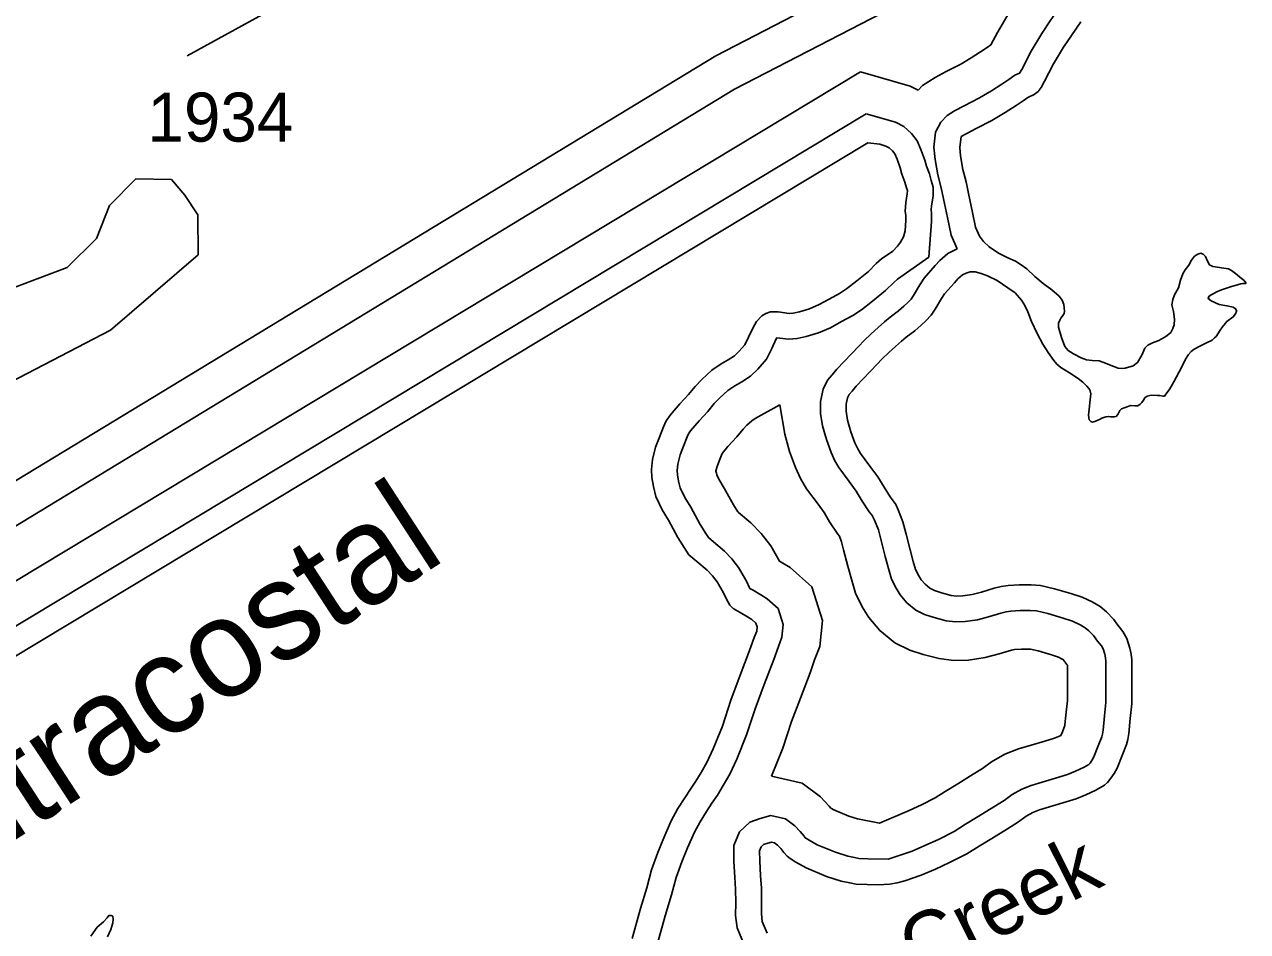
# Model space of a CAD drawing. Extents: x 2104537 to 2336408, y 34176 to 229611.
# Drawn here: x 2136862 to 2139980, y 43568 to 45881 of the extents above; entities that cross this region are included whole.
import ezdxf

# ---------------------------------------------------------------- set-up
doc = ezdxf.new("R2010")
doc.units = 0
for name, color, linetype in [('Exist Hydrographic Buffer Line', 7, 'Continuous'), ('Exist Hydrographic Creek Single Shore', 7, 'Continuous'), ('Exist Hydrographic Intracoastal Waterway Label', 7, 'Continuous'), ('Exist Hydrographic Misc Water Feature', 7, 'Continuous'), ('Exist Hydrographic River Shore', 7, 'Continuous'), ('Exist Road Secondary Type 51 Attributed', 7, 'Continuous'), ('Exist Road Secondary Type 51 Number Label', 7, 'Continuous'), ('Old_Level_32', 7, 'Continuous')]:
    doc.layers.add(name, color=color, linetype=linetype)

msp = doc.modelspace()

# ---------------------------------------------------------------- linework, layer by layer
at = {"layer": 'Exist Hydrographic Buffer Line'}
for p, q in [((2136210.3, 44335.1), (2138624.3, 45801.3)), ((2136263.7, 44252.4), (2138672.5, 45715.5))]:
    msp.add_line(p, q, dxfattribs=at)
for points in [[(2138624.3, 45801.3), (2139896.7, 46459.7), (2140167.9, 46542.5)], [(2139433.5, 45999.8), (2139396.3, 45945.9), (2139372.5, 45911.1), (2139342.3, 45860.3), (2139325.9, 45828.6), (2139316.7, 45822.6), (2139299.5, 45810.9), (2139275.7, 45795.4), (2139249.2, 45779.7), (2139212.1, 45760.8), (2139183.4, 45745.4), (2139151.6, 45725), (2139140.1, 45713.1)], [(2139506.6, 45932.4), (2139477.4, 45890.1), (2139455.5, 45858.1), (2139428.3, 45812.5), (2139404.4, 45766.1), (2139399.1, 45757.1), (2139387.2, 45751.2), (2139371.6, 45740.8), (2139353.9, 45728.9), (2139327.6, 45711.8), (2139296.7, 45693.5), (2139257.8, 45673.6), (2139233.2, 45660.4), (2139214.5, 45648.4), (2139198.6, 45631.9), (2139185, 45605.9), (2139180.3, 45567.7), (2139183.5, 45536.8), (2139190.3, 45497.2), (2139198.8, 45464.7), (2139204.8, 45435.9), (2139215, 45388.2), (2139224.2, 45343.6), (2139239.7, 45309)], [(2135551.7, 43635), (2135826.5, 43851.3), (2138993.8, 45759.8)], [(2138993.8, 45759.8), (2139119.7, 45723.8), (2139140.1, 45713.1)], [(2135662.8, 43597.1), (2135882.5, 43770.1), (2139007.9, 45653.4)], [(2139007.9, 45653.4), (2139082.9, 45631.9), (2139104.3, 45620.7), (2139123.8, 45602.8), (2139137.6, 45583.8), (2139147.4, 45562.1), (2139157.5, 45534.5), (2139161.3, 45519.5), (2139169.1, 45499.9), (2139173.8, 45482.9), (2139178.8, 45466.3), (2139178.3, 45443.1), (2139174.2, 45418.5), (2139173.2, 45407.8), (2139174.7, 45399.6), (2139174.8, 45378.6), (2139167.3, 45287.1)], [(2139167.3, 45287.1), (2139088.1, 45231.6), (2139078.6, 45223.1), (2139057.4, 45202.1), (2139024.4, 45175.4), (2138995.8, 45153.4), (2138973.9, 45138.8), (2138945.2, 45123.2), (2138916.7, 45107.4), (2138886.1, 45094.3), (2138854.6, 45084.9), (2138831.7, 45079.7), (2138810.1, 45078), (2138780.4, 45082), (2138778.8, 45078.8), (2138767, 45054.7), (2138753.4, 45027.1), (2138731.6, 45001.6), (2138712.7, 44984.3), (2138691, 44969.7), (2138672.9, 44959.5), (2138655.3, 44947.7), (2138634.7, 44928.7), (2138620.7, 44913.9), (2138604, 44894), (2138581.7, 44869.7), (2138560.4, 44844.6), (2138555.2, 44837.3), (2138551.5, 44829.3), (2138542.3, 44805.2), (2138533.7, 44783), (2138527.9, 44759.6), (2138526.1, 44743.4), (2138526.6, 44732.6), (2138529.7, 44716.4), (2138533.8, 44699.2), (2138545.4, 44674.4), (2138560.7, 44649.5), (2138584.3, 44606), (2138599, 44582.6), (2138605.7, 44572.4), (2138618.5, 44561.2), (2138646.9, 44537.5), (2138665.6, 44518.1), (2138682.7, 44496.1), (2138702.6, 44461.5), (2138710.8, 44443.8), (2138711.5, 44442.5), (2138719.8, 44438), (2138739.6, 44426), (2138755.6, 44416.2), (2138783.9, 44391.3), (2138796.6, 44350.7), (2138793, 44317.9), (2138784.1, 44294.5), (2138772.3, 44261.3), (2138748.2, 44197.9), (2138724.9, 44135.7), (2138703, 44069.1), (2138677.8, 44007), (2138660.2, 43968.7), (2138643.5, 43939.7), (2138628.9, 43915.4), (2138614.6, 43894.7), (2138601.2, 43873.4), (2138584.5, 43847.7), (2138570, 43821), (2138552.5, 43780.8), (2138537.7, 43745.1), (2138523.1, 43705.5), (2138511.9, 43661.1), (2138495.8, 43608), (2138475.5, 43536.7)], [(2139239.7, 45309), (2139216.4, 45296.6), (2139195.6, 45278.9), (2139183.9, 45265.9)], [(2139183.9, 45265.9), (2139155.9, 45233.9), (2139144.4, 45216.9)], [(2139144.4, 45216.9), (2139128.3, 45189.7), (2139122.3, 45180.6), (2139113.8, 45171.7), (2139103.6, 45162.2), (2139090.6, 45150.4), (2139068.9, 45134.7), (2139054.9, 45122.3), (2139038.7, 45108.3), (2139020.6, 45091.6), (2139002.1, 45073.8), (2138989.1, 45060.6), (2138932.9, 45001.9), (2138921.3, 44987.4), (2138909.4, 44973.4), (2138898, 44951), (2138891.2, 44919.6), (2138891.1, 44888.9), (2138896.5, 44857.6), (2138906.4, 44822.2), (2138918.5, 44789.1), (2138928.1, 44768.4), (2138938.1, 44751), (2138964.5, 44715.6), (2138982.5, 44690.7), (2138998, 44665.5), (2139015.8, 44638.3), (2139024.1, 44627.5), (2139024.4, 44627), (2139029.2, 44616.8), (2139039.1, 44592.3), (2139045.9, 44565.2), (2139056.4, 44524.2), (2139064.7, 44493.2), (2139072.8, 44466.4), (2139084.4, 44443.1), (2139094.6, 44426.3), (2139111.7, 44406.1), (2139134.6, 44387.4), (2139157, 44376.5), (2139181.3, 44368.1), (2139212.1, 44360.3), (2139236, 44357.3), (2139260.1, 44357.9), (2139291.4, 44362.8), (2139320.1, 44370.1), (2139351.6, 44379.9), (2139364.5, 44383.1), (2139376.4, 44384.7), (2139400.6, 44386.2), (2139425.8, 44386.5), (2139441.9, 44385.1), (2139471.4, 44378.3), (2139510, 44366.9), (2139534.2, 44359), (2139553.8, 44349.9), (2139566.5, 44342.5), (2139575.7, 44334.7), (2139587.7, 44322.3), (2139597.6, 44308.5), (2139608, 44295.8), (2139612.2, 44288.3), (2139616.5, 44274.8), (2139618.1, 44265.5), (2139619.2, 44256.8), (2139619.3, 44219.1), (2139619.2, 44178.8), (2139619.3, 44151.7), (2139615.9, 44117.6), (2139612.2, 44081.4), (2139610.4, 44071.1), (2139608.7, 44064.3), (2139599.7, 44040.9), (2139588.4, 44013), (2139583.9, 44005.1), (2139578.7, 43997.2), (2139575.4, 43993.2), (2139563.7, 43986.4), (2139541.7, 43976.5), (2139521.1, 43967.8), (2139491, 43959), (2139456.9, 43948.8), (2139428.3, 43940.2), (2139404.4, 43930.6), (2139380.5, 43917.2), (2139359.3, 43901.9), (2139333.2, 43885.5), (2139293.5, 43860.8), (2139261.5, 43841), (2139232.1, 43822.5), (2139191.9, 43802.3), (2139157.8, 43786.7), (2139125, 43772.4), (2139063.9, 43752.1)], [(2139063.9, 43752.1), (2139012.3, 43753.1), (2138989.6, 43754.1), (2138978.3, 43756.1), (2138961.1, 43759.6), (2138929.3, 43769.8), (2138883, 43789.1), (2138862.6, 43800.4), (2138851.6, 43807.6), (2138849.4, 43810.4), (2138839.5, 43822.7), (2138825.8, 43837), (2138802.3, 43854.6), (2138765.1, 43863.2), (2138737.6, 43855.9), (2138711.2, 43846.5), (2138685.2, 43821.6), (2138670.6, 43787), (2138670.8, 43745.8), (2138672.8, 43705.8), (2138675.1, 43675.3), (2138675.3, 43641.9), (2138675, 43608.7), (2138678.9, 43576.6), (2138696.6, 43533.5)]]:
    msp.add_lwpolyline(points, dxfattribs=at)
at = {"layer": 'Exist Hydrographic Creek Single Shore'}
for points in [[(2138672.5, 45715.5), (2139934, 46368.1), (2140187.4, 46445.5)], [(2139555.4, 45887.6), (2139531.4, 45852.9), (2139510.8, 45822.8), (2139485.7, 45780.6), (2139461.9, 45734.5), (2139453.7, 45720.5), (2139446, 45710.2), (2139436, 45702.2), (2139420.1, 45694.3), (2139408.1, 45686.3), (2139390.2, 45674.2), (2139362.2, 45656), (2139328.4, 45636), (2139288.3, 45615.5), (2139249.8, 45594.8)], [(2139249.8, 45594.8), (2139246.3, 45567.1), (2139248.5, 45545.7), (2139254.4, 45511.1), (2139262.7, 45479.8), (2139269, 45449.5), (2139279.2, 45401.7), (2139287, 45363.8), (2139297.1, 45341.3), (2139307, 45327.3), (2139321.2, 45313.9), (2139345.5, 45297.7), (2139369.2, 45285.8), (2139388.7, 45277.2), (2139403.3, 45268), (2139417.6, 45257.9), (2139437.5, 45237.9), (2139459.5, 45220), (2139481.5, 45204.2), (2139499.9, 45188.1), (2139507.9, 45178.1), (2139511.9, 45166.5), (2139512.8, 45158.3), (2139513.9, 45150.1), (2139513.1, 45143.5), (2139507.7, 45136.4), (2139504, 45131.6), (2139502, 45126.7), (2139498.5, 45119.2), (2139498.3, 45108.7), (2139506, 45082.3), (2139514.1, 45059.8), (2139523.1, 45049.2), (2139536.1, 45040.7), (2139556.2, 45030.5), (2139569.3, 45026), (2139584, 45024), (2139602, 45023), (2139618.3, 45016.8), (2139632.3, 45011), (2139650.2, 45004.7), (2139659.7, 45003.9), (2139668.3, 45004.4), (2139688.4, 45010.5), (2139700, 45018.5), (2139710.3, 45037.4), (2139718.1, 45055.3), (2139725.8, 45063.3), (2139738.1, 45068.7), (2139754, 45074.9), (2139771.9, 45085.4), (2139779.5, 45090.8), (2139784.5, 45095.6), (2139790, 45105.4), (2139793.5, 45115.2), (2139794.1, 45129.3), (2139791.8, 45149), (2139787.5, 45165.5), (2139789.8, 45179.2), (2139793.6, 45191.6), (2139803.8, 45209.5), (2139809.4, 45229), (2139815.3, 45245.3), (2139821.4, 45255.1), (2139830.2, 45267), (2139837.3, 45279.4), (2139845.4, 45289.7), (2139853.4, 45295.5), (2139861.3, 45297.6), (2139867.2, 45295.2), (2139873.3, 45289.2), (2139878, 45276.9), (2139883.4, 45267.6), (2139891.5, 45263.5), (2139919.6, 45259.7), (2139931.4, 45257.9), (2139939.5, 45253.4), (2139949.2, 45246), (2139965, 45233.3), (2139971.5, 45227.6)], [(2135736.8, 43571.9), (2135919.9, 43716), (2139011.9, 45579.2)], [(2139011.9, 45579.2), (2139042.4, 45575.3), (2139058.4, 45570.7), (2139066.2, 45566.6), (2139074.6, 45558.9), (2139080.6, 45550.6), (2139086.6, 45537.3), (2139094.7, 45515.2), (2139098.7, 45499.4), (2139106.8, 45478.9), (2139110.8, 45464.7), (2139113, 45457.4), (2139112.8, 45449.2), (2139109.1, 45427), (2139107, 45405), (2139109.1, 45393.5), (2139109.2, 45381), (2139107.1, 45354.8), (2139103.1, 45339.5), (2139095.3, 45325.5), (2139087.9, 45315.8), (2139075.5, 45302.9)], [(2139075.5, 45302.9), (2139047.3, 45283.1), (2139033.6, 45270.9), (2139013.5, 45251), (2138983.8, 45226.9), (2138957.5, 45206.8), (2138939.9, 45195), (2138913.7, 45180.7), (2138887.8, 45166.4), (2138863.7, 45156.1), (2138837.9, 45148.4), (2138821.8, 45144.7), (2138811.9, 45144), (2138783.8, 45147.8), (2138764.1, 45148.2), (2138751.9, 45143.5), (2138741.9, 45138.1), (2138727.9, 45123.6), (2138720, 45108), (2138708.1, 45083.6), (2138698.2, 45063.5), (2138684.4, 45047.3), (2138672, 45036.1), (2138656.4, 45025.5), (2138638.5, 45015.4), (2138614.6, 44999.4), (2138588.5, 44975.3), (2138571.8, 44957.6), (2138554.6, 44937.3), (2138532.5, 44913.1), (2138508.7, 44885), (2138498.2, 44870.4), (2138491, 44854.8), (2138481, 44828.8), (2138471, 44802.7), (2138463.2, 44771), (2138460.4, 44745.5), (2138461.3, 44725.1), (2138465.4, 44702.7), (2138471.5, 44677.4), (2138487.6, 44643.3), (2138503.8, 44616.7), (2138527.6, 44572.9), (2138543.8, 44547), (2138555.9, 44528.7), (2138575.9, 44511.3), (2138602.1, 44489.5), (2138615.9, 44475.1), (2138628.1, 44459.4), (2138644.3, 44431.2), (2138652.5, 44413.7), (2138660.4, 44399.7), (2138668.5, 44391.4), (2138687, 44381.2), (2138705.4, 44370), (2138716.5, 44363.2), (2138726.8, 44354.2), (2138729.9, 44344.3), (2138728.7, 44333.4), (2138722.5, 44317.2), (2138710.7, 44283.9), (2138686.8, 44221.1), (2138663, 44157.5), (2138641.3, 44091.7), (2138617.6, 44033.1), (2138601.8, 43998.9), (2138586.9, 43972.9), (2138573.7, 43950.9), (2138559.8, 43930.8), (2138545.9, 43908.8), (2138528, 43881.2), (2138511, 43849.7), (2138492.1, 43806.4), (2138476.6, 43769), (2138460.4, 43725), (2138448.6, 43678.7), (2138432.9, 43626.5), (2138411, 43549.8)], [(2139971.5, 45227.6), (2139975.7, 45221.6), (2139975.6, 45219.9), (2139967.4, 45220.1), (2139963.5, 45219.5), (2139937.1, 45211.8), (2139913.6, 45204.1), (2139903.7, 45200), (2139887.5, 45191.4), (2139881.5, 45187.3), (2139879.7, 45181.7), (2139887.8, 45175.7), (2139907.7, 45167.1), (2139927.6, 45163.4), (2139943.9, 45159.8), (2139949.8, 45155.8), (2139951.7, 45151.5), (2139952, 45149.8), (2139949.9, 45143.3), (2139943.8, 45135.2), (2139927.8, 45123.4), (2139916.1, 45109.5), (2139910, 45101.4), (2139899.8, 45085.2), (2139895.8, 45081.4), (2139890.1, 45075.6), (2139873.9, 45067.7), (2139858.7, 45060.7), (2139844.4, 45052.8), (2139836.1, 45047.1), (2139830, 45039), (2139821.9, 45027), (2139812.4, 45007.5), (2139792.3, 44969.2), (2139782.4, 44951.3), (2139770.6, 44935.1), (2139768.3, 44932.9), (2139764.3, 44933), (2139756.5, 44934.7), (2139750.3, 44934.9), (2139734.5, 44935.2), (2139724.6, 44932.7), (2139718.3, 44928.9), (2139714.6, 44923.1), (2139710.5, 44916.6), (2139706.5, 44912.7), (2139700.5, 44908.6), (2139692.7, 44908.7), (2139682.5, 44908.9), (2139668.6, 44904.3), (2139658.7, 44900.5), (2139654.7, 44896.4), (2139650.6, 44888.2), (2139648.6, 44885), (2139644.9, 44881.1), (2139640.6, 44880.2), (2139631.1, 44880.4), (2139624.9, 44881.5), (2139618.6, 44880.6), (2139608.7, 44876.9), (2139604.7, 44874.3), (2139596.8, 44870.6), (2139590.8, 44868.1), (2139584.9, 44866.5), (2139580.7, 44868.3), (2139576.8, 44872.6), (2139574.7, 44884.8), (2139580.4, 44938.8), (2139578.6, 44946.4), (2139576.4, 44952), (2139570.3, 44958.7), (2139560.3, 44968.7), (2139548.3, 44978.1), (2139526.3, 44992.3), (2139504.2, 45005.9), (2139494.2, 45014.3), (2139486.2, 45024.3), (2139472.2, 45044.3), (2139458.1, 45065.9), (2139443.9, 45092.4), (2139429.7, 45123.8), (2139419.7, 45148), (2139411.8, 45166.2), (2139403.9, 45177.8), (2139387.8, 45196.2), (2139369.4, 45209.6), (2139341.5, 45228.2), (2139317.5, 45240.2), (2139301.2, 45246.1), (2139285.5, 45249.7), (2139273.4, 45249.9), (2139262.5, 45246.8), (2139253.5, 45242.1), (2139241.5, 45231.8), (2139233, 45222.3)], [(2139233, 45222.3), (2139208, 45193.7), (2139199.9, 45181.7)], [(2139199.9, 45181.7), (2139183.9, 45154.8), (2139173.8, 45139.6), (2139160, 45125.1), (2139148, 45113.8), (2139132, 45099.4), (2139110, 45083.4), (2139098, 45072.8), (2139082.3, 45059.3), (2139065.6, 45043.9), (2139048.2, 45027.2), (2139036.2, 45014.9), (2138982.3, 44958.6), (2138971.8, 44945.6), (2138964.5, 44936.9), (2138960.4, 44928.8), (2138956.8, 44912.4), (2138956.7, 44894.4), (2138960.6, 44872), (2138968.9, 44842.3), (2138979.1, 44814.2), (2138986.4, 44798.7), (2138993.1, 44787.1), (2139017.4, 44754.4), (2139037.2, 44727.1), (2139053.4, 44700.6), (2139069.3, 44676.3), (2139079.6, 44663), (2139083.1, 44656.4), (2139089.4, 44643.1), (2139101.6, 44612.7), (2139109.5, 44581.4), (2139119.9, 44540.8), (2139127.8, 44511.1), (2139134, 44490.7), (2139141.9, 44474.8), (2139147.9, 44464.8), (2139157.9, 44453.1), (2139170.2, 44443), (2139182.2, 44437.2), (2139200.1, 44431), (2139224.3, 44424.9), (2139239.3, 44423), (2139254.1, 44423.4), (2139278.1, 44427.2), (2139302.2, 44433.3), (2139333.9, 44443.2), (2139352.4, 44447.7), (2139370.1, 44450), (2139398.1, 44451.8), (2139428.3, 44452.2), (2139452.2, 44450.1), (2139488.1, 44441.8), (2139529.5, 44429.6), (2139558.2, 44420.1), (2139584.2, 44408.1), (2139604.4, 44396.3), (2139620.5, 44382.8), (2139638.2, 44364.5), (2139649.7, 44348.5), (2139662.5, 44332.8), (2139672.7, 44314.6), (2139680.4, 44290.5), (2139683.1, 44275), (2139684.8, 44260.8), (2139684.9, 44219.2), (2139684.8, 44178.8), (2139684.9, 44148.6), (2139681.2, 44111), (2139677.2, 44072.3), (2139674.6, 44057.6), (2139671.4, 44044.5), (2139660.7, 44016.9), (2139647.6, 43984.3), (2139639.8, 43970.7), (2139631.7, 43958.4), (2139623.3, 43948), (2139615.6, 43940.6), (2139593.7, 43927.9), (2139567.9, 43916.3), (2139543.1, 43905.9), (2139509.7, 43896.1), (2139475.7, 43885.9), (2139450, 43878.2), (2139432.8, 43871.3), (2139415.9, 43861.8), (2139395.9, 43847.4), (2139368, 43829.9), (2139328.2, 43805.1), (2139296.3, 43785.3), (2139264.4, 43765.3), (2139220.3, 43743.2), (2139184.6, 43726.8), (2139148.5, 43711.1), (2139106.6, 43697.1), (2139087.1, 43691.6), (2139067.7, 43688.7)], [(2139067.7, 43688.7), (2139038.8, 43687), (2139010.2, 43687.5), (2138982.4, 43688.7), (2138966, 43691.6), (2138944.4, 43696), (2138906.6, 43708.2), (2138854.5, 43729.9), (2138828.6, 43744.2), (2138814.3, 43753.6), (2138806.2, 43759.4), (2138798.2, 43769.4), (2138790.2, 43779.4), (2138782.1, 43787.7), (2138774.1, 43793.8), (2138766.2, 43795.6), (2138757, 43793.1), (2138746.4, 43789.4), (2138740.4, 43783.6), (2138736.3, 43773.8), (2138736.4, 43747.6), (2138738.3, 43709.8), (2138740.7, 43677.9), (2138740.9, 43641.8), (2138740.7, 43612.3), (2138743, 43593.2), (2138755.4, 43563.2)], [(2137073.4, 43554.3), (2137082.2, 43572.8), (2137087.2, 43590.1), (2137088, 43598.9), (2137087.2, 43606.5), (2137083.3, 43608.2), (2137077, 43608.3), (2137073, 43602.5), (2137063.3, 43592.2), (2137047.2, 43578.4), (2137031.4, 43555.7)]]:
    msp.add_lwpolyline(points, dxfattribs=at)
at = {"layer": 'Exist Hydrographic Misc Water Feature'}
msp.add_lwpolyline([(2135842.8, 44163.8), (2135816.8, 44380.8), (2136173.8, 44816.9), (2136621.8, 45077.3), (2136771.9, 45186), (2136970.8, 45260.9), (2137045.8, 45334.9), (2137078.9, 45419.6), (2137145.9, 45487.2), (2137236.7, 45485.5), (2137270.8, 45445.4), (2137303.8, 45395.6), (2137304.8, 45293.8), (2137080.9, 45101.3), (2136697.9, 44902), (2136581.8, 44766.4), (2136240.8, 44582.7), (2136166.8, 44488.9), (2136174.8, 44390.3)], dxfattribs=at)
at = {"layer": 'Exist Hydrographic River Shore'}
for points in [[(2138787.4, 44911.2), (2138724.5, 44875.6), (2138716.4, 44870.2), (2138704, 44858.7), (2138694.2, 44848.4), (2138677.9, 44829), (2138655.6, 44804.6), (2138640.7, 44787.1), (2138634.1, 44769.9), (2138627.8, 44753.4), (2138625, 44742.3), (2138625, 44742), (2138626, 44736.8), (2138627.1, 44732), (2138632.2, 44721.2), (2138646, 44698.6), (2138669.3, 44655.7), (2138680.6, 44637.7), (2138682.4, 44636.1), (2138714.1, 44609.6), (2138740.1, 44582.6), (2138764.7, 44551), (2138786.8, 44512.5), (2138790.9, 44510), (2138814.2, 44495.7), (2138869.7, 44447), (2138896.7, 44360.4), (2138889.4, 44294.6), (2138876.4, 44260.5), (2138864.7, 44227.4), (2138840.3, 44163.1), (2138817.7, 44103.1), (2138795.5, 44035.2), (2138766.5, 43963.8)], [(2138787.4, 44911.2), (2138800.3, 44836), (2138812.6, 44792), (2138827.5, 44751.3), (2138840.6, 44723.1), (2138855.7, 44696.9), (2138885.2, 44657.2), (2138900.6, 44636.1), (2138914.8, 44612.8), (2138935.6, 44581.2), (2138939.6, 44576), (2138945.3, 44561.8), (2138950.5, 44540.9), (2138961.2, 44499.3), (2138970.1, 44466.2), (2138980.9, 44430.1), (2138998.1, 44395.6), (2139014.5, 44368.5), (2139042.5, 44335.6), (2139081.2, 44303.9), (2139119.3, 44285.4), (2139153.1, 44273.7), (2139193.8, 44263.5), (2139230.9, 44258.7), (2139269, 44259.7), (2139311.2, 44266.3), (2139346.8, 44275.4), (2139378.1, 44285.1), (2139382.6, 44286.2), (2139385.7, 44286.6), (2139404.3, 44287.8), (2139422.1, 44288), (2139426.5, 44287.7), (2139446.4, 44283.1), (2139480.6, 44272.9), (2139498.1, 44267.2), (2139508, 44262.6), (2139509.1, 44262), (2139511.9, 44259.1), (2139519.5, 44248.5), (2139520.8, 44247), (2139520.9, 44219.1), (2139520.8, 44178.9), (2139520.8, 44156.4), (2139518, 44127.4), (2139514.6, 44095), (2139514.3, 44093), (2139508.1, 44077.1), (2139504.3, 44067.5), (2139502.6, 44066.8), (2139488.1, 44060.7), (2139463, 44053.3), (2139428.7, 44043.1), (2139395.9, 44033.2), (2139361.8, 44019.6), (2139327.4, 44000.3), (2139304.3, 43983.6), (2139281, 43969), (2139241.6, 43944.4), (2139209.4, 43924.5), (2139183.7, 43908.4), (2139149.3, 43891.1), (2139117.7, 43876.6), (2139042, 43843.6)], [(2139042, 43843.6), (2138986, 43855), (2138963.4, 43862.2), (2138925.8, 43877.9), (2138918, 43882.2), (2138913.5, 43887.7), (2138891.2, 43911), (2138844.6, 43945.9), (2138766.5, 43963.8)]]:
    msp.add_lwpolyline(points, dxfattribs=at)
at = {"layer": 'Exist Road Secondary Type 51 Attributed'}
msp.add_lwpolyline([(2139129.2, 46865.1), (2138974.7, 46638), (2138865.2, 46527.6), (2138747.6, 46417), (2138668.1, 46342.7), (2138617.8, 46356.5), (2138513.5, 46426.1), (2138477.5, 46433.7), (2138296.1, 46347), (2138212.1, 46300.7), (2137913, 46151.3), (2137276.3, 45801.2)], dxfattribs=at)

# ---------------------------------------------------------------- texts
at = {"layer": 'Exist Hydrographic Intracoastal Waterway Label'}
msp.add_text('Intracostal', height=250, rotation=33.0676, dxfattribs=at).set_placement((2136648.8, 43677.5))
at = {"layer": 'Exist Road Secondary Type 51 Number Label'}
msp.add_text('1934', height=125, dxfattribs=at).set_placement((2137175.5, 45582.1))
at = {"layer": 'Old_Level_32'}
msp.add_text('Creek', height=150, rotation=26.732, dxfattribs=at).set_placement((2139141.8, 43446.4))

doc.saveas('drawing.dxf')
